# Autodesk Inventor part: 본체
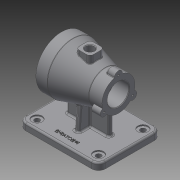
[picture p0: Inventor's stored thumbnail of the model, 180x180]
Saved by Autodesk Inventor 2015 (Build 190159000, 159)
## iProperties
Created: 2021-10
Part Number: 본체
Material: 일반
Document SubType Name: Modeling
Designer: 1016549
Density: 1 g/cm^3
Appearance: 기본값
Author: 1016549
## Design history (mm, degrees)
sketch "스케치1"
  geometry: L1 (70, 55)-(-70, 55); L2 (-70, 55)-(-70, -55); L3 (-70, -55)-(70, -55); L4 (70, -55)-(70, 55); L5 (70, 55)-(-70, -55); L6 (-70, 55)-(70, -55); 1 further point
  constraints: 12 end point, 2 midpoint, 2 parallel, 1 horizontal, 1 perpendicular
  dimensions: "d0" = 110 distance of L3.end L1.start; "d1" = 140 distance of L2.end L3.end
extrude "돌출1" new body sketch "스케치1" distance "d2" = 12; taper "d3" = 0 deg
fillet "모깎기1" dims "d4" = 12
sketch "스케치3"
  geometry: L1 (70, 0)-(-70, 0) reference; L2 (-70, 0)-(-70, 12) reference; L3 (-70, 12)-(70, 12) reference; L4 (70, 12)-(70, 0) reference; L5 (50, 127)-(30, 127); L6 (-50, 111)-(-50, 82); L7 (-50, 82)-(50, 82); L8 (50, 82)-(50, 127); L9 (30, 127)-(-27, 111); L10 (-27, 111)-(-50, 111); 3 further points
  constraints: 12 end point, 2 horizontal, 2 midpoint, 2 parallel, 1 perpendicular, 1 vertical alignment
  dimensions: "d13" = 82 distance between parallel lines of L1 L7; "d14" = 20 distance from line of L5.end L8; "d15" = 23 distance from line of L6 L9.end; "d16" = 90 diameter of L5 L7; "d17" = 58 diameter of L10 L7; "d18" = 100 distance between parallel lines of L6 L8
revolve "회전1" sketch "스케치3" stored, may be unused: angle "d19" = 90 deg
sketch "스케치4"
  geometry: L1 (37, 4)-(-37, 4); L2 (-37, 4)-(-37, -4); L3 (-37, -4)-(37, -4); L4 (37, -4)-(37, 4); L5 (37, 4)-(-37, -4); L6 (-37, 4)-(37, -4); L7 (-4, 24)-(4, 24); L8 (4, 24)-(4, -24); L9 (4, -24)-(-4, -24); L10 (-4, -24)-(-4, 24); L11 (-4, 24)-(4, -24); L12 (4, 24)-(-4, -24); 2 further points
  constraints: 24 end point, 6 midpoint, 4 parallel, 2 horizontal, 2 perpendicular
  dimensions: "d20" = 8 distance of L3.end L1.start; "d21" = 74 distance of L1.start L1.end; "d22" = 8 distance of L7.start L7.end; "d23" = 48 distance of L7.end L8.end
extrude "돌출2" join sketch "스케치4" distance "d24" = 70; taper "d25" = 0 deg
feature "면 기울기1" dims angle "d26" = 5 deg
fillet "모깎기2" dims "d27" = 3
fillet "모깎기3" dims "d28" = 3
sketch "스케치6"
  geometry: C1 r 7 at (-29, 0); 2 further points
  constraints: 1 centre point, 1 horizontal alignment, 1 other
  dimensions: "d32" = 7 radius of C1
extrude "돌출4" join sketch "스케치6" distance "d33" = 15; taper "d34" = 0 deg
node "작업 평면1"
sketch "스케치7"
  geometry: L1 (-34, -4)-(-30, -4) reference; L2 (-30, -4)-(-30, 4) reference; L3 (-30, 4)-(-34, 4) reference; L4 (-37, 1)-(-37, -1) reference; L5 (-50, 45)-(-50, -45) reference; L6 (-4, -7)-(-4, -17.773) reference; L7 (4, -17.559)-(4, -7) reference; L8 (7, -4)-(27, -4) reference; L9 (27, -4)-(27, 4) reference; L10 (27, 4)-(7, 4) reference; L11 (4, 7)-(4, 17.559) reference; L12 (-4, 17.773)-(-4, 7) reference; L13 (-7, 4)-(-30, 4) reference; L14 (-30, -4)-(-30, 4) reference; L15 (-30, -4)-(-7, -4) reference; L16 (27, 29)-(-30, 45) reference; L17 (27, -29)-(-30, -45) reference; L18 (12.5, -12.5)-(-12.5, -12.5); L19 (-12.5, -12.5)-(-12.5, 12.5); L20 (-12.5, 12.5)-(12.5, 12.5); L21 (12.5, 12.5)-(12.5, -12.5); L22 (12.5, -12.5)-(-12.5, 12.5); L23 (-12.5, -12.5)-(12.5, 12.5); 5 further points
  constraints: 12 end point, 2 midpoint, 2 parallel, 1 horizontal, 1 perpendicular, 12 other
  dimensions: "d39" = 25 distance of L20.end L18.start; "d40" = 25 distance of L18.start L18.end
extrude "돌출5" join sketch "스케치7" stored distance "d41" = 15; taper "d42" = 0 deg
fillet "모깎기4" dims "d43" = 6
fillet "모깎기5" dims "d44" = 3
fillet "모깎기6" dims "d45" = 1
sketch "스케치8"
  geometry: C1 r 45 at (0, 0) reference; 1 further point
hole "구멍2" sketch "스케치8" at (0, 0) diameter "d46" = 62; stored, may be unused: countersink angle "d50" = 90 deg, drill point angle "d52" = 0 deg; dims "d47" = 6, "d48" = 62, "d49" = 23, "d51" = 23
sketch "스케치9"
  geometry: C1 r 31 at (0, 0) reference; 1 further point
hole "구멍3" sketch "스케치9" at (0, 0) diameter "d53" = 50; stored, may be unused: countersink angle "d57" = 90 deg, drill point angle "d59" = 0 deg; dims "d54" = 6, "d55" = 62, "d56" = 23, "d58" = 47
sketch "스케치10"
  geometry: A1 r 29 centre (29, 0) between (49.095, -20.909) and (49.095, 20.909) reference; 1 further point
hole "구멍4" sketch "스케치10" at (29, 0) diameter "d60" = 38; stored, may be unused: countersink angle "d64" = 90 deg, drill point angle "d66" = 0 deg; dims "d61" = 6, "d62" = 62, "d63" = 23, "d65" = 30
sketch "스케치11"
  geometry: C1 r 31 at (0, 0) reference; 2 further points
  constraints: 1 horizontal alignment
  dimensions: "d67" = 40 distance of C1.centre point (40, 0)
hole "구멍5" sketch "스케치11" at (40, 0) diameter "d68" = 3.242; stored, may be unused: countersink angle "d72" = 90 deg, drill point angle "d74" = 118 deg; dims "d69" = 9, "d70" = 62, "d71" = 23, "d73" = 11
sketch "스케치12"
  geometry: A1 r 7 centre (43.5, 25.115) between (49.095, 20.909) and (37.06, 27.858) reference; A2 r 7 centre (0, 0) between (0.845, 6.949) and (0.845, -6.949) reference; A3 r 7 centre (43.5, -25.115) between (37.06, -27.858) and (49.095, -20.909) reference; 2 further points
hole "구멍6" sketch "스케치12" at (40.806, 124.368), (0, 0), (43.5, -25.115), (43.5, 25.115) diameter "d78" = 3.242; stored, may be unused: countersink angle "d82" = 90 deg, drill point angle "d84" = 118 deg; dims "d79" = 9, "d80" = 62, "d81" = 23, "d83" = 11
sketch "스케치13"
  geometry: 1 further point
hole "구멍7" sketch "스케치13" at (0, 0) diameter "d85" = 15; stored, may be unused: countersink angle "d89" = 90 deg, drill point angle "d91" = 118 deg; dims "d86" = 9, "d87" = 62, "d88" = 23, "d90" = 20
fillet "모깎기7" dims "d92" = 3
fillet "모깎기8" dims "d93" = 1
sketch "스케치14"
  geometry: L1 (-58, -55)-(58, -55) reference; 2 further points
  constraints: 1 vertical alignment, 1 other
  dimensions: "d94" = 15 distance from line of L1 point (0, -40)
feature "엠보싱1" sketch "스케치14" dims "d13" = 82, "d14" = 20, "d15" = 23, "d16" = 90, "d17" = 58, "d18" = 100, "d95" = 0.5, "d96" = 0
fillet "모깎기9" dims "d97" = 3
fillet "모깎기10" dims "d98" = 3
fillet "모깎기11" dims "d99" = 3
chamfer "모따기1" distance "d100" = 1; stored, may be unused: second distance "d101" = 2, angle "d102" = 45 deg
chamfer "모따기2" distance "d103" = 1; stored, may be unused: second distance "d104" = 2, angle "d105" = 45 deg
sketch "스케치15"
  geometry: L1 (58, 55)-(-58, 55) reference; L2 (-70, 43)-(-70, -43) reference; 2 further points
  dimensions: "d106" = 16 distance from line of point (-54, 39) L1; "d107" = 16 distance from line of point (-54, 39) L2
hole "구멍8" sketch "스케치15" at (-54, 39) diameter "d108" = 9; stored, may be unused: countersink angle "d112" = 90 deg, drill point angle "d114" = 118 deg; dims "d109" = 9, "d110" = 18, "d111" = 2, "d113" = 20
fillet "모깎기12" dims "d121" = 3
node "솔리드1"
pattern_circular "원형 패턴1" dims angle "d36" = 360 deg
pattern_circular "원형 패턴2" dims angle "d76" = 360 deg
pattern_linear "직사각형 패턴1" dims "d117" = 108
pattern_linear "직사각형 패턴2" dims "d120" = 78
node "투영된 루프1"
node "투영된 루프2"
node "절단 모서리 투영1"
other parameters: "d38" = 127
